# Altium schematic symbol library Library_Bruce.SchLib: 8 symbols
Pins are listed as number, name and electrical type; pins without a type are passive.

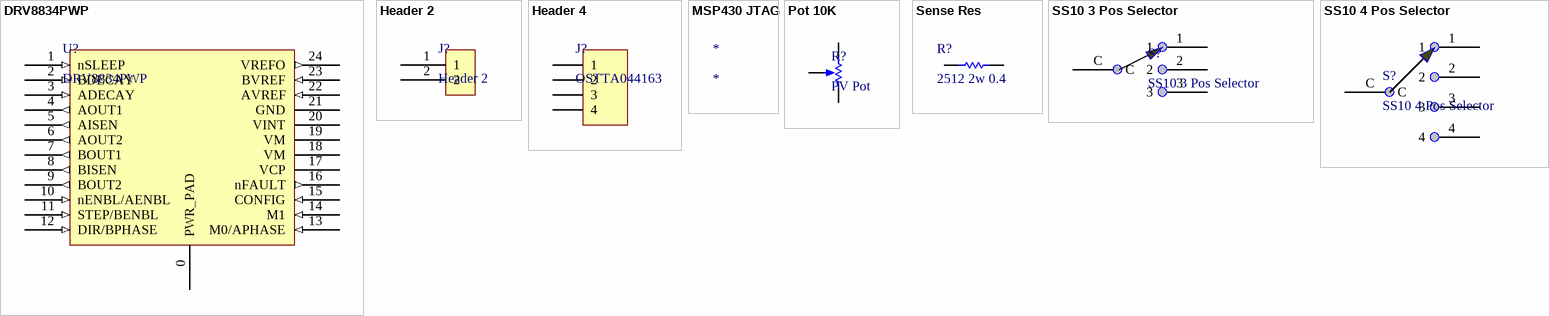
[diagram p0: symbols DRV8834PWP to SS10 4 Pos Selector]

## DRV8834PWP
designator U?
Stepping and DC motor Driver; Manufacturer: Texas Instruments
pins: 0 PWR_PAD (power), 1 nSLEEP (in), 2 BDECAY (in), 3 ADECAY (in), 4 AOUT1 (out), 5 AISEN (out), 6 AOUT2 (out), 7 BOUT1 (out), 8 BISEN (out), 9 BOUT2 (out), 10 nENBL/AENBL (in), 11 STEP/BENBL (in), 12 DIR/BPHASE (in), 13 M0/APHASE (in), 14 M1 (in), 15 CONFIG (in), 16 nFAULT (out), 17 VCP (power), 18 VM (power), 19 VM (power), 20 VINT (power), 21 GND (power), 22 AVREF (in), 23 BVREF (in), 24 VREFO (out)

## Header 2
designator J?
pins: 1, 2

## Header 4
designator J?, comment OSTTA044163
TERM BLOCK 5.08MM VERT 4POS PCB; Manufacturer: On Shore Technology Inc; DK Part Number: ED2583-ND
pins: 1, 2, 3, 4

## MSP430 JTAG
designator *

## Pot 10K
designator R?, comment PV Pot
TRIMMER 10K OHM 0.25W TH; Manufacturer: Murata Electronics North America; MFG Part number: PV37Y103C01B00; DK Part Number: 490-3008-ND
pins: 1 TOP, 2 TAP, 3 BOT

## Sense Res
designator R?, comment 2512 2w 0.4
RES .4OHM 2W 1% 2512 SMD; Manufacturer: Stackpole; MFG Part Number: CSRN2512FKR400; DK Part Number: CSRN2512FKR400TR-ND; Value: 0.4
pins: 1, 2

## SS10 3 Pos Selector
designator S?
pins: 1, 2, 3, C

## SS10 4 Pos Selector
designator S?
pins: 1, 2, 3, 4, C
